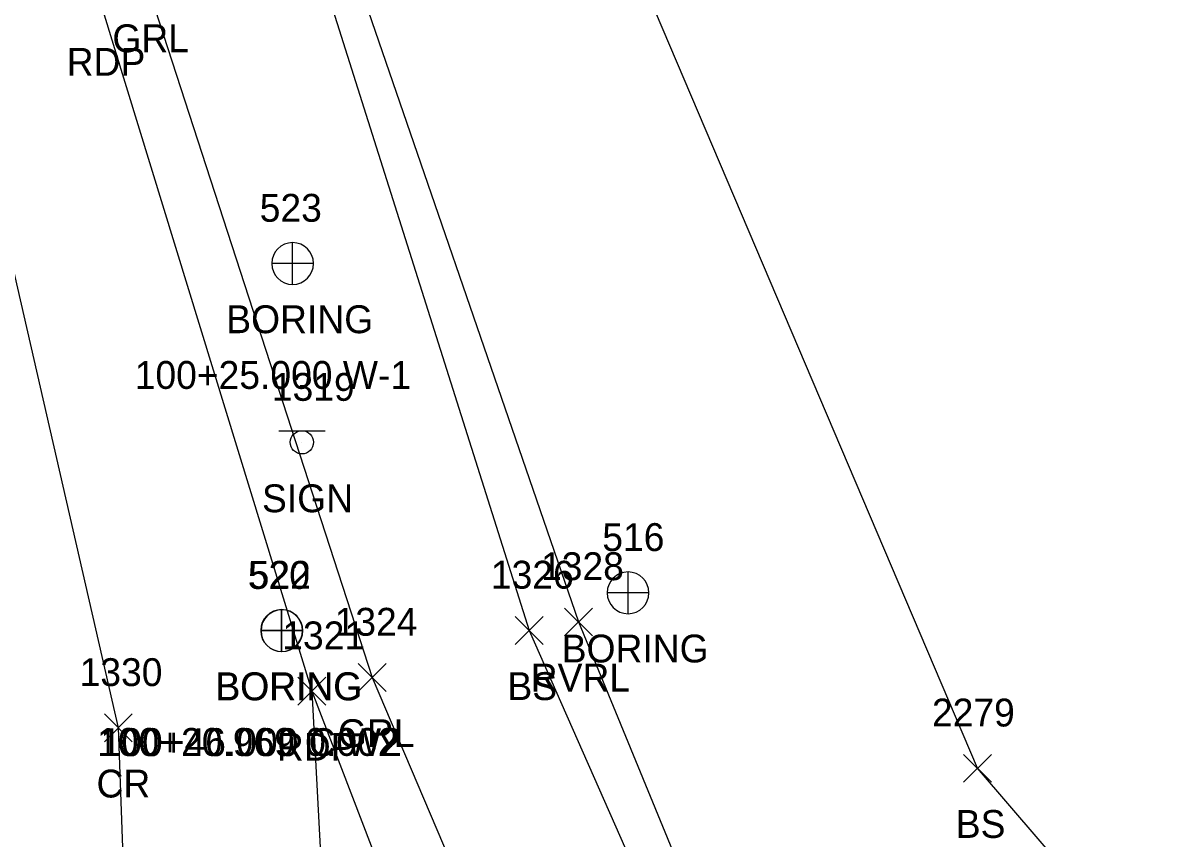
# Model space of a CAD drawing. Extents: x 1509053 to 1511576, y 400838 to 402572.
# Drawn here: x 1509792.1 to 1509874.8, y 401655.6 to 401714.2 of the extents above; entities that cross this region are included whole.
import ezdxf

# ---------------------------------------------------------------- set-up
doc = ezdxf.new("R2010")
doc.units = 0
for name, color, linetype in [('G_A', 7, 'Continuous'), ('G_C', 7, 'Continuous'), ('G_I', 7, 'Continuous'), ('GA_P', 7, 'Continuous'), ('L_A', 7, 'Continuous'), ('L_I', 7, 'Continuous'), ('L_TIC', 7, 'Continuous'), ('LAWE', 7, 'Continuous'), ('LELB', 7, 'Continuous'), ('P_A', 7, 'Continuous'), ('P_I', 7, 'Continuous'), ('P_TIC', 7, 'Continuous'), ('PET', 7, 'Continuous'), ('PRC', 7, 'Continuous'), ('R_A', 7, 'Continuous'), ('R_I', 7, 'Continuous'), ('R_TIC', 7, 'Continuous'), ('RGR', 7, 'Continuous'), ('S_A', 7, 'Continuous'), ('S_I', 7, 'Continuous'), ('SSGN', 7, 'Continuous')]:
    doc.layers.add(name, color=color, linetype=linetype)

msp = doc.modelspace()

# ---------------------------------------------------------------- linework, layer by layer
at = {"layer": 'GA_P'}
for p, q in [((1509811.449, 401696.941), (1509811.449, 401698.441)), ((1509811.449, 401696.941), (1509809.949, 401696.941)), ((1509812.949, 401696.941), (1509811.449, 401696.941)), ((1509811.449, 401695.441), (1509811.449, 401696.941)), ((1509835.54, 401673.3), (1509835.54, 401674.8)), ((1509835.54, 401673.3), (1509834.04, 401673.3)), ((1509837.04, 401673.3), (1509835.54, 401673.3)), ((1509835.54, 401671.8), (1509835.54, 401673.3)), ((1509810.655, 401670.591), (1509810.655, 401672.091)), ((1509810.68, 401670.579), (1509810.68, 401672.079)), ((1509810.655, 401670.591), (1509809.155, 401670.591)), ((1509810.68, 401670.579), (1509809.18, 401670.579)), ((1509812.155, 401670.591), (1509810.655, 401670.591)), ((1509810.655, 401669.091), (1509810.655, 401670.591)), ((1509812.18, 401670.579), (1509810.68, 401670.579)), ((1509810.68, 401669.079), (1509810.68, 401670.579))]:
    msp.add_line(p, q, dxfattribs=at)
for centre, start, end in [((1509811.449, 401696.941), 90, 180), ((1509811.449, 401696.941), 0, 90), ((1509811.449, 401696.941), 180, 270), ((1509811.449, 401696.941), 270, 0), ((1509835.54, 401673.3), 90, 180), ((1509835.54, 401673.3), 0, 90), ((1509835.54, 401673.3), 180, 270), ((1509835.54, 401673.3), 270, 0), ((1509810.655, 401670.591), 90, 180), ((1509810.68, 401670.579), 90, 180), ((1509810.655, 401670.591), 0, 90), ((1509810.68, 401670.579), 0, 90), ((1509810.655, 401670.591), 180, 270), ((1509810.68, 401670.579), 180, 270), ((1509810.655, 401670.591), 270, 0), ((1509810.68, 401670.579), 270, 0)]:
    msp.add_arc(centre, 1.5, start, end, dxfattribs=at)
at = {"layer": 'L_TIC'}
for points in [[(1509830.984, 401670.209), (1509832.984, 401672.209)], [(1509832.984, 401670.209), (1509830.984, 401672.209)], [(1509827.436, 401669.599), (1509829.436, 401671.599)], [(1509829.436, 401669.599), (1509827.436, 401671.599)], [(1509859.636, 401659.703), (1509861.636, 401661.703)], [(1509861.636, 401659.703), (1509859.636, 401661.703)]]:
    msp.add_lwpolyline(points, dxfattribs=at)
at = {"layer": 'LAWE'}
for points in [[(1509105.869, 402324.243), (1509166.85, 402316.837), (1509211.487, 402305.132), (1509268.211, 402284.91), (1509312.964, 402259.071), (1509356.201, 402241.452), (1509401.109, 402232.663), (1509452.564, 402212.798), (1509514.156, 402192.045), (1509556.38, 402176.059), (1509631.867, 402126.974), (1509661.731, 402089.308), (1509701.865, 402034.143), (1509721.261, 402000.814), (1509742.127, 401921.738), (1509766.755, 401859.141), (1509782.515, 401819.754), (1509797.905, 401768.024), (1509814.098, 401723.168), (1509831.984, 401671.209)], [(1509831.984, 401671.209), (1509850.64, 401625.872)]]:
    msp.add_lwpolyline(points, dxfattribs=at)
at = {"layer": 'LELB'}
for points in [[(1509893.599, 401622.332), (1509860.636, 401660.703), (1509835.457, 401719.882), (1509820.452, 401775.667), (1509804.552, 401821.184), (1509793.576, 401877.466), (1509769.389, 401921.128), (1509750.313, 401995.309), (1509714.668, 402043.058), (1509675.87, 402101.276), (1509636.96, 402136.162), (1509603.466, 402183.374), (1509565.384, 402200.628), (1509506.188, 402219.725), (1509454.311, 402229.611), (1509409.3, 402242.421), (1509343.868, 402268.781), (1509286.853, 402299.311), (1509229.317, 402329.052), (1509168.375, 402334.875), (1509111.415, 402354.712)], [(1509776.115, 401814.53), (1509791.866, 401766.045), (1509811.956, 401722.659), (1509828.436, 401670.599)], [(1509828.436, 401670.599), (1509848.096, 401626.091)]]:
    msp.add_lwpolyline(points, dxfattribs=at)
at = {"layer": 'P_TIC'}
for points in [[(1509811.832, 401665.242), (1509813.832, 401667.242)], [(1509813.832, 401665.242), (1509811.832, 401667.242)], [(1509811.832, 401665.242), (1509813.832, 401667.242)], [(1509813.832, 401665.242), (1509811.832, 401667.242)], [(1509797.931, 401662.604), (1509799.931, 401664.604)], [(1509799.931, 401662.604), (1509797.931, 401664.604)]]:
    msp.add_lwpolyline(points, dxfattribs=at)
at = {"layer": 'PET'}
for points in [[(1509715.312, 401901.724), (1509745.325, 401858.521), (1509766.293, 401811.158), (1509783.046, 401763.871), (1509797.735, 401715.42), (1509812.832, 401666.242)], [(1509812.832, 401666.242), (1509822.152, 401641.967), (1509832.572, 401624.959), (1509838.993, 401621.028), (1509861.826, 401615.769), (1509863.366, 401606.462)], [(1509812.832, 401666.242), (1509816.404, 401599.338)]]:
    msp.add_lwpolyline(points, dxfattribs=at)
at = {"layer": 'PRC'}
for points in [[(1509707.243, 401894.157), (1509736.222, 401853.246), (1509757.098, 401807.737), (1509773.383, 401760.444), (1509787.688, 401712.52), (1509798.931, 401663.604)], [(1509798.931, 401663.604), (1509801.323, 401597.39)]]:
    msp.add_lwpolyline(points, dxfattribs=at)
at = {"layer": 'R_TIC'}
for points in [[(1509816.159, 401666.219), (1509818.159, 401668.219)], [(1509818.159, 401666.219), (1509816.159, 401668.219)]]:
    msp.add_lwpolyline(points, dxfattribs=at)
at = {"layer": 'RGR'}
for points in [[(1509718.965, 401902.892), (1509748.047, 401859.65), (1509768.468, 401812.012), (1509784.687, 401764.48), (1509800.961, 401717.112), (1509817.159, 401667.219)], [(1509817.159, 401667.219), (1509834.776, 401625.828)]]:
    msp.add_lwpolyline(points, dxfattribs=at)
at = {"layer": 'SSGN'}
for p, q in [((1509810.466, 401684.939), (1509813.799, 401684.939)), ((1509812.113, 401684.105), (1509812.113, 401684.105))]:
    msp.add_line(p, q, dxfattribs=at)
msp.add_circle((1509812.113, 401684.105), 0.833, dxfattribs=at)

# ---------------------------------------------------------------- texts
at = {"layer": 'G_A'}
for p in [(1509806.685, 401691.941), (1509830.776, 401668.3), (1509805.891, 401665.591), (1509805.917, 401665.579)]:
    msp.add_text('BORING', height=2, dxfattribs=at).set_placement(p)
at = {"layer": 'G_C'}
for s, p in [('100+25.000 W-1', (1509800.11, 401687.941)), ('100+20.969 0.002', (1509797.411, 401661.591)), ('100+46.000 C W2', (1509797.657, 401661.579))]:
    msp.add_text(s, height=2, dxfattribs=at).set_placement(p)
at = {"layer": 'G_I'}
for s, p in [('523', (1509809.087, 401699.941)), ('516', (1509833.69, 401676.3)), ('520', (1509808.232, 401673.579)), ('522', (1509808.293, 401673.591))]:
    msp.add_text(s, height=2, dxfattribs=at).set_placement(p)
at = {"layer": 'L_A'}
for s, p in [('RVRL', (1509828.551, 401666.209)), ('BS', (1509826.877, 401665.599)), ('BS', (1509859.077, 401655.703))]:
    msp.add_text(s, height=2, dxfattribs=at).set_placement(p)
at = {"layer": 'L_I'}
for s, p in [('1328', (1509829.291, 401674.209)), ('1326', (1509825.688, 401673.599)), ('2279', (1509857.368, 401663.703))]:
    msp.add_text(s, height=2, dxfattribs=at).set_placement(p)
at = {"layer": 'P_A'}
for s, p in [('RDP', (1509795.223, 401710.42)), ('RDP', (1509810.32, 401661.242)), ('RDP', (1509810.32, 401661.242)), ('CR', (1509797.364, 401658.604))]:
    msp.add_text(s, height=2, dxfattribs=at).set_placement(p)
at = {"layer": 'P_I'}
for s, p in [('1321', (1509810.706, 401669.242)), ('1321', (1509810.706, 401669.242)), ('1330', (1509796.151, 401666.604))]:
    msp.add_text(s, height=2, dxfattribs=at).set_placement(p)
at = {"layer": 'R_A'}
for p in [(1509798.504, 401712.112), (1509814.702, 401662.219)]:
    msp.add_text('GRL', height=2, dxfattribs=at).set_placement(p)
at = {"layer": 'R_I'}
msp.add_text('1324', height=2, dxfattribs=at).set_placement((1509814.466, 401670.219))
at = {"layer": 'S_A'}
msp.add_text('SIGN', height=2, dxfattribs=at).set_placement((1509809.25, 401679.085))
at = {"layer": 'S_I'}
msp.add_text('1319', height=2, dxfattribs=at).set_placement((1509809.959, 401687.085))

doc.saveas('drawing.dxf')
